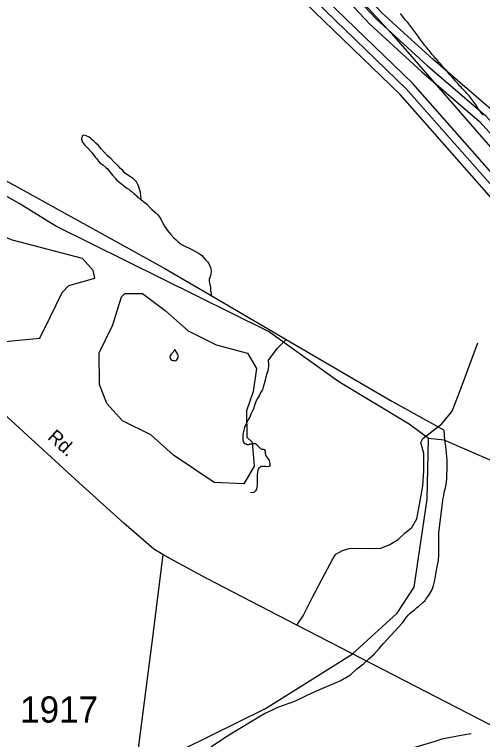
# Model space of a CAD drawing. Extents: x 2206922 to 2357709, y 510027 to 673830.
# Drawn here: x 2302180 to 2304412, y 573478 to 576938 of the extents above; entities that cross this region are included whole.
import ezdxf

# ---------------------------------------------------------------- set-up
doc = ezdxf.new("R2010")
doc.units = 0
for name, color, linetype in [('Exist Boundary Land Use Reservation Military US Department of Defense', 7, 'Continuous'), ('Exist Boundary Political City Limit New', 7, 'Continuous'), ('Exist Hydrographic Buffer Line', 7, 'Continuous'), ('Exist Hydrographic Creek Single Shore', 7, 'Continuous'), ('Exist Hydrographic Misc Water Feature', 7, 'Continuous'), ('Exist Hydrographic Pond Under 1500 Sq Ft', 7, 'Continuous'), ('Exist Hydrographic River Shore', 7, 'Continuous'), ('Exist Road Non-System Type 51', 7, 'Continuous'), ('Exist Road Primary NC Attributed', 7, 'Continuous'), ('Exist Road Primary NC Label', 7, 'Continuous'), ('Exist Road Secondary Type 51 Attributed', 7, 'Continuous'), ('Exist Road Secondary Type 51 Number Label', 7, 'Continuous'), ('Map Preparation Boundary City Limit Buffer Line', 7, 'Continuous')]:
    doc.layers.add(name, color=color, linetype=linetype)

msp = doc.modelspace()

# ---------------------------------------------------------------- linework, layer by layer
at = {"layer": 'Exist Boundary Land Use Reservation Military US Department of Defense'}
msp.add_lwpolyline([(2302653.7, 578219.3), (2302707.5, 578135.4), (2303467.5, 577403.4), (2303978.9, 576846.8), (2304504.6, 576243.3), (2304908.4, 575801.8)], dxfattribs=at)
at = {"layer": 'Exist Boundary Political City Limit New'}
for points in [[(2304133.2, 576797.1), (2304128.2, 576803.4), (2304123.5, 576809.8), (2304118.8, 576816.2), (2304114, 576822.6), (2304109, 576829), (2304104.2, 576835.4), (2304099.5, 576841.8), (2304094.8, 576848.2), (2304090, 576854.7), (2304085.2, 576861.1), (2304080.5, 576867.6), (2304075.8, 576873.9), (2304070.8, 576880.2), (2304065.8, 576886.6), (2304061, 576892.8), (2304055.8, 576899.1), (2304050.8, 576905.2), (2304045.8, 576911.4), (2304040.8, 576917.6), (2304035.5, 576923.8), (2304025.5, 576936.3), (2304020.8, 576942.6)], [(2304413.8, 576458.6), (2304409, 576465.1), (2304404.2, 576471.6), (2304399.8, 576478.2), (2304395.2, 576484.8), (2304390.8, 576491.4), (2304386.2, 576498.1), (2304381.8, 576504.7), (2304377.2, 576511.2), (2304372.5, 576517.8), (2304368, 576524.3), (2304363.2, 576530.7), (2304358.2, 576537.1), (2304353.2, 576543.2), (2304348.2, 576549.4), (2304343, 576555.4), (2304337.5, 576561.4), (2304332.2, 576567.3), (2304326.8, 576573.1), (2304321.2, 576579), (2304315.8, 576584.8), (2304310.2, 576590.6), (2304304.8, 576596.5), (2304299.5, 576602.4), (2304294, 576608.4), (2304288.8, 576614.4), (2304283.5, 576620.4), (2304278.2, 576626.4), (2304273, 576632.4), (2304267.8, 576638.4), (2304262.5, 576644.4), (2304257.2, 576650.5), (2304252, 576656.5), (2304246.8, 576662.6), (2304241.5, 576668.6), (2304236.2, 576674.6), (2304230.8, 576680.7), (2304225.5, 576686.7), (2304220.2, 576692.7), (2304215, 576698.7), (2304209.8, 576704.7), (2304204.5, 576710.7), (2304199.2, 576716.7), (2304193.8, 576722.7), (2304188.5, 576728.7), (2304183.2, 576734.8), (2304178, 576740.8), (2304173, 576746.9), (2304167.8, 576753), (2304162.8, 576759.2), (2304157.8, 576765.4), (2304152.8, 576771.7), (2304147.8, 576778), (2304143, 576784.3), (2304138, 576790.7), (2304133.2, 576797.1)]]:
    msp.add_lwpolyline(points, dxfattribs=at)
at = {"layer": 'Exist Hydrographic Buffer Line'}
for points in [[(2300867.3, 579578.6), (2301645.5, 579388.8), (2301915.1, 579278), (2302124, 579135.4), (2302277, 578931.1), (2302463.4, 578496.9), (2302527.4, 578430.9), (2302677.5, 578176), (2303727.1, 577108.2), (2303903.9, 576918.9), (2304150.2, 576693.6), (2304426.2, 576456.1), (2304701.8, 576152.7), (2304792.4, 576024), (2304953.6, 575800.4), (2305360.8, 575344.7), (2305655.5, 574989.7), (2307819.2, 572880.8), (2307961.3, 572692.2), (2308367.4, 572421.9), (2308632.6, 572285.3)], [(2307829.6, 572652.2), (2307342.6, 573143.5), (2306887.4, 573566), (2306818.1, 573617.1), (2306459.1, 573968.1), (2306180.6, 574206.8), (2305802.9, 574593.9), (2305700.4, 574650.5), (2305686.8, 574691.9), (2305256.8, 575202.8), (2305037.8, 575466.2), (2304918.7, 575590.8), (2304581.4, 575980.1), (2304050.1, 576582.4), (2303274.6, 577333.7), (2302654.1, 577998.3), (2302595.7, 578079.2), (2302513.2, 578191.5), (2302174.9, 578860.6), (2301990.8, 579065.7), (2301618, 579231.6), (2300673.5, 579390.2), (2299998.5, 579350.7)], [(2302414.8, 578475.1), (2302495.8, 578405.9), (2302643, 578155.7), (2303698.4, 577080.5), (2303874.6, 576891.6), (2304123.1, 576664), (2304398.1, 576427.4), (2304670.6, 576127.7), (2304759.6, 576001), (2304921.2, 575777), (2305330.7, 575318.6), (2305624.7, 574964.2), (2307789, 572854.3)], [(2307876.2, 572691.5), (2307370.9, 573171.7), (2306914.7, 573595.4), (2306843.9, 573647.8), (2306487.1, 573996.7), (2306207.9, 574236.1), (2305831.4, 574621.8), (2305735.6, 574677.1), (2305717.4, 574717.7), (2305287.4, 575228.5), (2305068.6, 575491.8), (2304948.4, 575617.8), (2304611.5, 576006.3), (2304080, 576608.9), (2303303.1, 577361.7), (2302685.1, 578023.8), (2302627.9, 578102.6), (2302547.5, 578212.4), (2302414.8, 578475.1)]]:
    msp.add_lwpolyline(points, dxfattribs=at)
at = {"layer": 'Exist Hydrographic Creek Single Shore'}
for points in [[(2299494, 574647), (2299537.9, 574425.6), (2299528.1, 573798.5), (2299586.9, 573676.2), (2299773.1, 573486.8), (2299982.1, 573380.4), (2300126, 573140.1), (2300288, 572841.5), (2300321, 572816.5), (2300355.1, 572742.5), (2300499, 572567.8), (2300607.1, 572513.1), (2300782, 572595.6), (2301451.1, 573052.5), (2302291.2, 573139), (2302582.1, 573232.7), (2303377.1, 573625.8), (2303791.1, 573885.4), (2304005.2, 574081.1), (2304087, 574205.8), (2304149.1, 574625.1), (2304155.1, 574914)], [(2305665.1, 574624), (2305591.1, 574565.2), (2305391.1, 574563.6), (2304790.1, 574680.5), (2304581.2, 574754.1), (2304230.1, 574907.2), (2304155.1, 574914)]]:
    msp.add_lwpolyline(points, dxfattribs=at)
at = {"layer": 'Exist Hydrographic Misc Water Feature'}
for points in [[(2304155.1, 574914), (2304062.2, 574982.5), (2303727.1, 575185.5), (2303391.1, 575424.6), (2302378.1, 575928.5), (2302202, 576036.2), (2301716, 576311.9), (2301356.1, 576527.1), (2301029.1, 576704.2), (2300954, 576720.8), (2300770.1, 576811.8), (2300519.1, 576841.1), (2300420.1, 576814.1), (2300128.1, 576805.6), (2300028, 576837.7), (2299445, 576879.7), (2299095, 576859), (2298945.9, 576800.5), (2298723.1, 576565.1), (2298592, 576362.9), (2298502, 576211.6)], [(2301638.1, 576410), (2302178.8, 576123.8), (2302896.7, 575725.8), (2303118.1, 575596.3)], [(2302779.4, 576058.5), (2302784.9, 576060.6), (2302783.1, 576072.6), (2302780.6, 576088.3), (2302778.8, 576100.4), (2302772.6, 576116.3), (2302768.7, 576126.3), (2302762.4, 576140.2), (2302748.2, 576154.1), (2302734.1, 576163.9), (2302716.2, 576173.9), (2302705.6, 576181.6), (2302698, 576191.6), (2302685.9, 576203.2), (2302675.4, 576215.3), (2302655.5, 576232.9), (2302639.3, 576250.7), (2302625.2, 576262.6), (2302608.6, 576280.5), (2302593, 576296.3), (2302580.3, 576312.4), (2302568.6, 576323.8), (2302560.2, 576332), (2302550.6, 576340), (2302542.4, 576347.7), (2302536, 576351.9), (2302521.8, 576359.7), (2302508.1, 576361.4), (2302502.4, 576357.4), (2302500.5, 576343.4), (2302504.6, 576329.4), (2302514.5, 576315.4), (2302528.8, 576301.4), (2302547.1, 576281.7), (2302557.1, 576268), (2302565.3, 576257.9), (2302571.3, 576250.1), (2302581.1, 576238.4), (2302589.7, 576228.2), (2302601.6, 576220.3), (2302615.8, 576208.5), (2302621.9, 576202.7), (2302648.2, 576171.2), (2302660.3, 576157.2), (2302666.2, 576149), (2302678.3, 576139.5), (2302690.6, 576129.5), (2302700.7, 576121.5), (2302708.6, 576115.8), (2302716.6, 576109.8), (2302725.1, 576104), (2302732.8, 576098), (2302740.8, 576091.9), (2302747.2, 576086.1), (2302756.8, 576078.1), (2302763, 576072.3), (2302768.9, 576064.6), (2302779.4, 576058.5)], [(2302779.4, 576058.5), (2302811.8, 576033), (2302825.7, 576017.1), (2302836, 576007), (2302845.6, 575999.1), (2302853.8, 575991.4), (2302863.9, 575981.3), (2302869.8, 575973.6), (2302880.5, 575957.8), (2302886, 575945.6), (2302896.3, 575927.8), (2302908.8, 575908.1), (2302925, 575890.3), (2302941, 575872.4), (2302951.2, 575862.3), (2302961.1, 575852.7), (2302977.5, 575840.6), (2302995.3, 575831), (2303013.6, 575823.4), (2303029.8, 575815.3), (2303043.7, 575807.5), (2303057.6, 575799.7), (2303071.8, 575789.8), (2303082, 575777.7), (2303092.1, 575766.1), (2303100.1, 575758), (2303106.5, 575750.2), (2303110.1, 575742.3), (2303114.7, 575730.3), (2303116.5, 575724.3), (2303118.8, 575712.2), (2303116.9, 575698.3), (2303115.1, 575692.1), (2303111.2, 575682.1), (2303109.1, 575676.4), (2303109.1, 575664.2), (2303111.6, 575650.5), (2303113.6, 575642.5), (2303115.7, 575632.4), (2303115.9, 575620.2), (2303117.7, 575606.5), (2303118.1, 575596.3)], [(2303118.1, 575596.3), (2303387.6, 575439.4), (2303476, 575386.3)], [(2303389.4, 575285.4), (2303414.8, 575319.7), (2303432.9, 575343.7), (2303476, 575386.3)], [(2303476, 575386.3), (2303979.2, 575092), (2304230.3, 574954.8)], [(2302944.9, 575338.6), (2302941, 575332.7), (2302936.9, 575326.8), (2302931.1, 575320.3), (2302927.2, 575316.5), (2302923.3, 575308.6), (2302921.3, 575304.4), (2302923.3, 575296.4), (2302929.3, 575288.6), (2302935.2, 575286.5), (2302939.1, 575286.7), (2302943.4, 575286.5), (2302947.3, 575284.6), (2302951.2, 575286.9), (2302955.1, 575290.8), (2302959.4, 575298.6), (2302961.5, 575302.8), (2302961.1, 575313), (2302957.4, 575318.8), (2302953.1, 575326.8), (2302944.9, 575338.6)], [(2303389.4, 575285.4), (2303391.5, 575271.3), (2303391.5, 575259.5), (2303389.6, 575247.7), (2303388, 575237.4), (2303383.9, 575223.4), (2303379.8, 575209.4), (2303375.9, 575193.4), (2303370.4, 575175.1), (2303366.9, 575159), (2303362.6, 575147.1), (2303354.8, 575135.3), (2303347.4, 575119), (2303339, 575104.9), (2303331.2, 575091), (2303325.7, 575072.8), (2303319.5, 575056.7), (2303314, 575042.9), (2303308, 575030.8), (2303302.3, 575016.7), (2303296.3, 575006.6), (2303288.1, 574990.4), (2303276.8, 574966.6), (2303271.1, 574942.3), (2303269.1, 574932.5), (2303269.1, 574926.4), (2303269.3, 574918.3), (2303269.5, 574908.5), (2303271.5, 574900.5), (2303275.6, 574892.6), (2303281.4, 574888.5), (2303285.7, 574888.6), (2303289.6, 574886.8), (2303293.9, 574886.6), (2303299.8, 574886.5), (2303303.5, 574888.8), (2303311.5, 574888.8), (2303317.4, 574891.1), (2303323.4, 574891), (2303329.3, 574890.9), (2303335.7, 574885.1), (2303339.6, 574881.3), (2303353.9, 574867.4), (2303360.1, 574863.2), (2303366, 574863.6), (2303371.6, 574861.5), (2303375.9, 574853.6), (2303375.9, 574843.4), (2303379.8, 574831.5), (2303388, 574819.7), (2303394.5, 574809.8), (2303396.4, 574803.8), (2303398.6, 574793.7), (2303398.6, 574786.1), (2303394.5, 574781.8), (2303384.3, 574779.7), (2303378.8, 574781.8), (2303368.5, 574781.6), (2303360.5, 574781.2), (2303354.6, 574781.3), (2303348.8, 574775.3), (2303344.7, 574771.4), (2303340.8, 574763.1), (2303338.8, 574753.3), (2303337.3, 574739.3), (2303337.5, 574725.1), (2303337.5, 574707.3), (2303337.7, 574693.4), (2303335.7, 574683.2), (2303334.1, 574673.3), (2303329.5, 574665.1), (2303322.4, 574657.2), (2303306.2, 574654.8)], [(2303116.9, 573443.6), (2303196.7, 573496.5), (2303230.3, 573516.6), (2303345.5, 573586), (2303373.2, 573602.1), (2303407.1, 573618.5), (2303437, 573633), (2303516.6, 573661.6), (2303544.6, 573674), (2303570.5, 573686.4), (2303596.3, 573698.7), (2303628.1, 573713), (2303691.5, 573741.5), (2303717.3, 573751.8), (2303733.3, 573758), (2303749.5, 573768.1), (2303759.5, 573772.3), (2303783.1, 573786.5), (2303812.9, 573814.9), (2303844.6, 573839.3), (2303870.3, 573863.4), (2303896.1, 573885.5), (2303919.7, 573912), (2303939.4, 573936.2), (2304028.6, 574033.1), (2304039.8, 574047.2), (2304050.3, 574061.4), (2304057.9, 574071.2), (2304064, 574077.2), (2304077.6, 574089.8), (2304087.8, 574097.5), (2304097.7, 574105.8), (2304109.2, 574113.8), (2304127, 574132.1), (2304138.9, 574142.1), (2304144.8, 574152.2), (2304155.1, 574164.4), (2304168.8, 574188.3), (2304174.2, 574198.5), (2304178.3, 574212.5), (2304184.4, 574238.7), (2304189.9, 574266.7), (2304195.3, 574294.7), (2304202.9, 574334.8), (2304204.7, 574360.9), (2304204.5, 574382.9), (2304203.9, 574434.9), (2304203.5, 574466.5), (2304222.3, 574604.8), (2304223.6, 574622.9), (2304227.9, 574642.9), (2304231.6, 574662.7), (2304235.1, 574678.8), (2304239, 574696.9), (2304242.8, 574721), (2304242.8, 574742.9), (2304244.3, 574767), (2304243.9, 574791), (2304243.9, 574812.9), (2304236.9, 574876.8), (2304233, 574908.6), (2304230.3, 574954.8)], [(2304358.1, 573504.9), (2304317.9, 573498.4), (2304218.2, 573479.4), (2304180.5, 573467.2), (2304072.9, 573435.9), (2304036.8, 573423.5), (2303919.9, 573372.2), (2303875.8, 573349.7), (2303812, 573319.1), (2303694.7, 573256.1), (2303673.2, 573243.9), (2303645.3, 573229.4), (2303621.3, 573215.2), (2303476.6, 573119.8), (2303456.9, 573105.3), (2303438.8, 573089.4), (2303419.2, 573072.9)]]:
    msp.add_lwpolyline(points, dxfattribs=at)
at = {"layer": 'Exist Hydrographic Pond Under 1500 Sq Ft'}
for points in [[(2302134.1, 575377.2), (2302301, 575393.7), (2302350, 575494.2), (2302407, 575611.3), (2302440, 575645.5), (2302564.1, 575680), (2302555.1, 575715.7), (2302505, 575772.8), (2302171, 575861), (2302003.1, 575926.4), (2301845, 575890.5), (2301788, 575779.9), (2301798, 575698.3), (2301857.1, 575615.3), (2302134.1, 575377.2)], [(2303132.1, 574705.4), (2302939.1, 574835.4), (2302830, 574932.7), (2302696.1, 574999.5), (2302620.1, 575081.8), (2302586, 575172.3), (2302584, 575323.1), (2302650, 575457), (2302690, 575589.9), (2302706, 575607), (2302790.1, 575607.1), (2302899.1, 575526.1), (2303008, 575428.8), (2303142.1, 575362.1), (2303292, 575322.2), (2303335.1, 575248.5), (2303319.1, 575139.5), (2303287.1, 575046.3), (2303288.1, 574921.7), (2303314.2, 574896.5), (2303323, 574782), (2303274.2, 574698), (2303132.1, 574705.4)]]:
    msp.add_lwpolyline(points, dxfattribs=at)
at = {"layer": 'Exist Hydrographic River Shore'}
for points in [[(2308936.9, 572246.2), (2308843.3, 572269.7), (2308644.3, 572320.4), (2308394.7, 572457), (2307993.3, 572716.3), (2307849.1, 572907.3), (2305686.2, 575015.3), (2305391.1, 575370.9), (2304986.2, 575823.8), (2304825.2, 576047), (2304733.1, 576177.8), (2304454.1, 576484.9), (2304177, 576723), (2303933, 576946.2), (2303756.1, 577136), (2302712.1, 578196.3), (2302559, 578455.9), (2302500.1, 578512.6), (2302312.1, 578951.3), (2302152.1, 579164.7), (2301934, 579313.4), (2301658, 579426.9), (2300873, 579618.3)], [(2305665.1, 574624), (2305656.1, 574666.2), (2305226.1, 575177.1), (2305007.1, 575440.6), (2304889.2, 575563.9), (2304551, 575953.9), (2304020.2, 576555.9), (2303246.1, 577305.6), (2302623.1, 577972.8), (2302563.1, 578055.8), (2302479, 578170.5), (2302139, 578842.6), (2301961, 579038.8), (2301602, 579194.9), (2300666.9, 579350.8), (2300000.9, 579310.8), (2298731.7, 578994.6), (2298446.2, 578890.4), (2298312.9, 578842.3)]]:
    msp.add_lwpolyline(points, dxfattribs=at)
at = {"layer": 'Exist Road Non-System Type 51'}
msp.add_lwpolyline([(2303527.6, 574023.9), (2303556.5, 574068.5), (2303602.3, 574157.7), (2303660.2, 574268.6), (2303698.8, 574341), (2303713.2, 574362.7), (2303730.1, 574372.3), (2303744.6, 574379.6), (2303775.9, 574389.2), (2303821.7, 574391.6), (2303882, 574389.2), (2303927.7, 574391.6), (2303971.1, 574408.5), (2304009.7, 574432.6), (2304043.4, 574464), (2304074.8, 574490.5), (2304098.9, 574531.5), (2304108.5, 574582.2), (2304127.8, 574688.3), (2304132.6, 574760.6), (2304132.6, 574842.6), (2304118.2, 574895.7), (2304127.8, 574915), (2304156.7, 574936.7), (2304217, 574982.5), (2304267.6, 575045.2), (2304311, 575156.2), (2304390.6, 575370.8)], dxfattribs=at)
at = {"layer": 'Exist Road Primary NC Attributed'}
for points in [[(2302887.5, 574360.5), (2302845.1, 574386.1), (2302701.1, 574510), (2302489, 574703), (2301745, 575383.1), (2300459.9, 576531)], [(2308561.8, 570519.5), (2308463.4, 570607.6), (2308398.6, 570680.2), (2308292.5, 570820), (2308179.9, 570972.9), (2308050.4, 571167.2), (2307884.7, 571418.5), (2307786.3, 571553.2), (2307594.3, 571804.7), (2307545.8, 571854.5), (2307500, 571902.7), (2307449.4, 571943.7), (2307360.2, 572013.6), (2307240.4, 572093.5), (2307106.6, 572173.3), (2306933.8, 572265.4), (2306089.9, 572703.4), (2304593, 573472.8), (2303939.8, 573810.4), (2303527.6, 574023.9), (2303094.8, 574247.9), (2302942.2, 574331.5), (2302887.5, 574360.5)]]:
    msp.add_lwpolyline(points, dxfattribs=at)
at = {"layer": 'Exist Road Secondary Type 51 Attributed'}
msp.add_lwpolyline([(2302887.5, 574360.5), (2302840.9, 573977.8), (2302680.3, 572735.8), (2302614.4, 572251.8), (2302580.6, 572036.4), (2302561.3, 571860.3), (2302566.2, 571757.4), (2302580.6, 571704.3), (2302609.5, 571635.2), (2302646.5, 571577.3), (2302693.1, 571519.4), (2302744.5, 571466.4), (2302900.4, 571324.9), (2303313.4, 570990.5), (2304081.5, 570361.8), (2304308.1, 570164)], dxfattribs=at)
at = {"layer": 'Map Preparation Boundary City Limit Buffer Line'}
for points in [[(2304133.2, 576797.1), (2304128.2, 576803.4), (2304123.5, 576809.8), (2304118.8, 576816.2), (2304114, 576822.6), (2304109, 576829), (2304104.2, 576835.4), (2304099.5, 576841.8), (2304094.8, 576848.2), (2304090, 576854.7), (2304085.2, 576861.1), (2304080.5, 576867.6), (2304075.8, 576873.9), (2304070.8, 576880.2), (2304065.8, 576886.6), (2304061, 576892.8), (2304055.8, 576899.1), (2304050.8, 576905.2), (2304045.8, 576911.4), (2304040.8, 576917.6), (2304035.5, 576923.8), (2304025.5, 576936.3), (2304020.8, 576942.6)], [(2304413.8, 576458.6), (2304409, 576465.1), (2304404.2, 576471.6), (2304399.8, 576478.2), (2304395.2, 576484.8), (2304390.8, 576491.4), (2304386.2, 576498.1), (2304381.8, 576504.7), (2304377.2, 576511.2), (2304372.5, 576517.8), (2304368, 576524.3), (2304363.2, 576530.7), (2304358.2, 576537.1), (2304353.2, 576543.2), (2304348.2, 576549.4), (2304343, 576555.4), (2304337.5, 576561.4), (2304332.2, 576567.3), (2304326.8, 576573.1), (2304321.2, 576579), (2304315.8, 576584.8), (2304310.2, 576590.6), (2304304.8, 576596.5), (2304299.5, 576602.4), (2304294, 576608.4), (2304288.8, 576614.4), (2304283.5, 576620.4), (2304278.2, 576626.4), (2304273, 576632.4), (2304267.8, 576638.4), (2304262.5, 576644.4), (2304257.2, 576650.5), (2304252, 576656.5), (2304246.8, 576662.6), (2304241.5, 576668.6), (2304236.2, 576674.6), (2304230.8, 576680.7), (2304225.5, 576686.7), (2304220.2, 576692.7), (2304215, 576698.7), (2304209.8, 576704.7), (2304204.5, 576710.7), (2304199.2, 576716.7), (2304193.8, 576722.7), (2304188.5, 576728.7), (2304183.2, 576734.8), (2304178, 576740.8), (2304173, 576746.9), (2304167.8, 576753), (2304162.8, 576759.2), (2304157.8, 576765.4), (2304152.8, 576771.7), (2304147.8, 576778), (2304143, 576784.3), (2304138, 576790.7), (2304133.2, 576797.1)]]:
    msp.add_lwpolyline(points, dxfattribs=at)

# ---------------------------------------------------------------- texts
at = {"layer": 'Exist Road Primary NC Label'}
msp.add_text('Rd.', height=65.62, rotation=317.6595, dxfattribs=at).set_placement((2302333.8, 574915.3))
at = {"layer": 'Exist Road Secondary Type 51 Number Label'}
msp.add_text('1917', height=125, dxfattribs=at).set_placement((2302207.1, 573559))

doc.saveas('drawing.dxf')
